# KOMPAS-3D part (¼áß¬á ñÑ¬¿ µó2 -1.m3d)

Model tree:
1. Эскиз:1
2. Операция выдавливания:1
     Толщина стенки 1 = 7; Толщина стенки 2 = 6; Расстояние 1 = 0.6
3. Эскиз:2
4. Вырезать элемент выдавливания:1
     Толщина стенки 2 = 15; Расстояние 1 = 10
5. Эскиз:3
6. Вырезать элемент выдавливания:2
     Толщина стенки 1 = 8; Толщина стенки 2 = 15; Расстояние 1 = 10
7. Эскиз:4
8. Вырезать элемент выдавливания:3
     Толщина стенки 1 = 7; Расстояние 1 = 10
9. Эскиз:6
10. Вырезать элемент выдавливания:5
     Толщина стенки 1 = 7; Расстояние 1 = 10
